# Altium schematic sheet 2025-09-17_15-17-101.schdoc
size 1045 x 355 mm; SheetNumber: 1; SheetTotal: 1
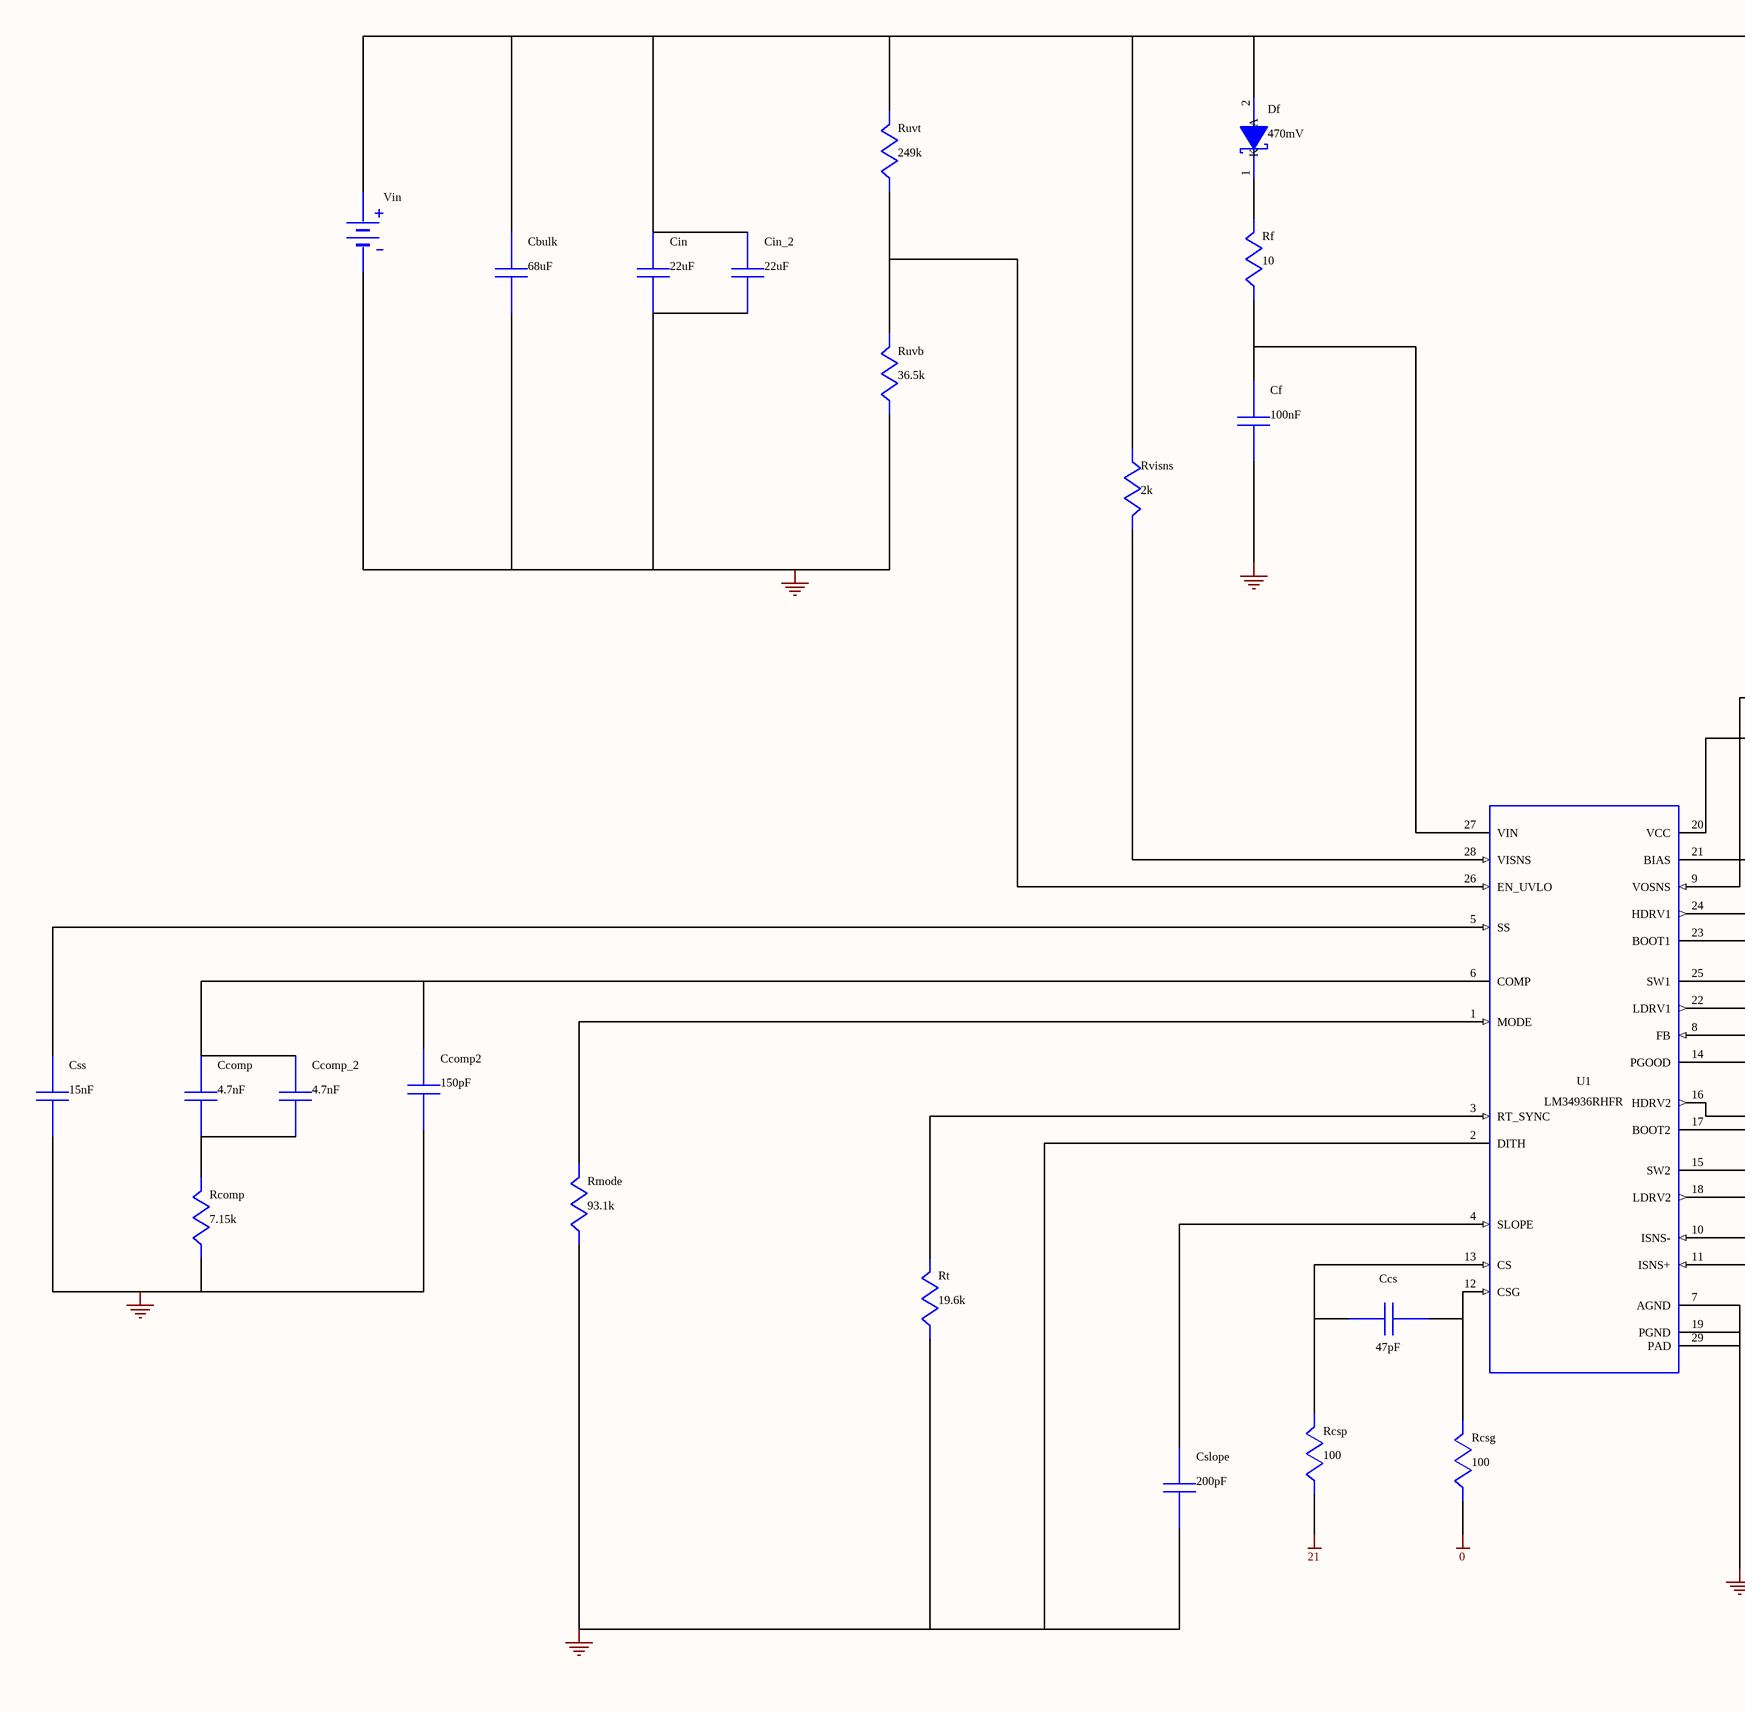
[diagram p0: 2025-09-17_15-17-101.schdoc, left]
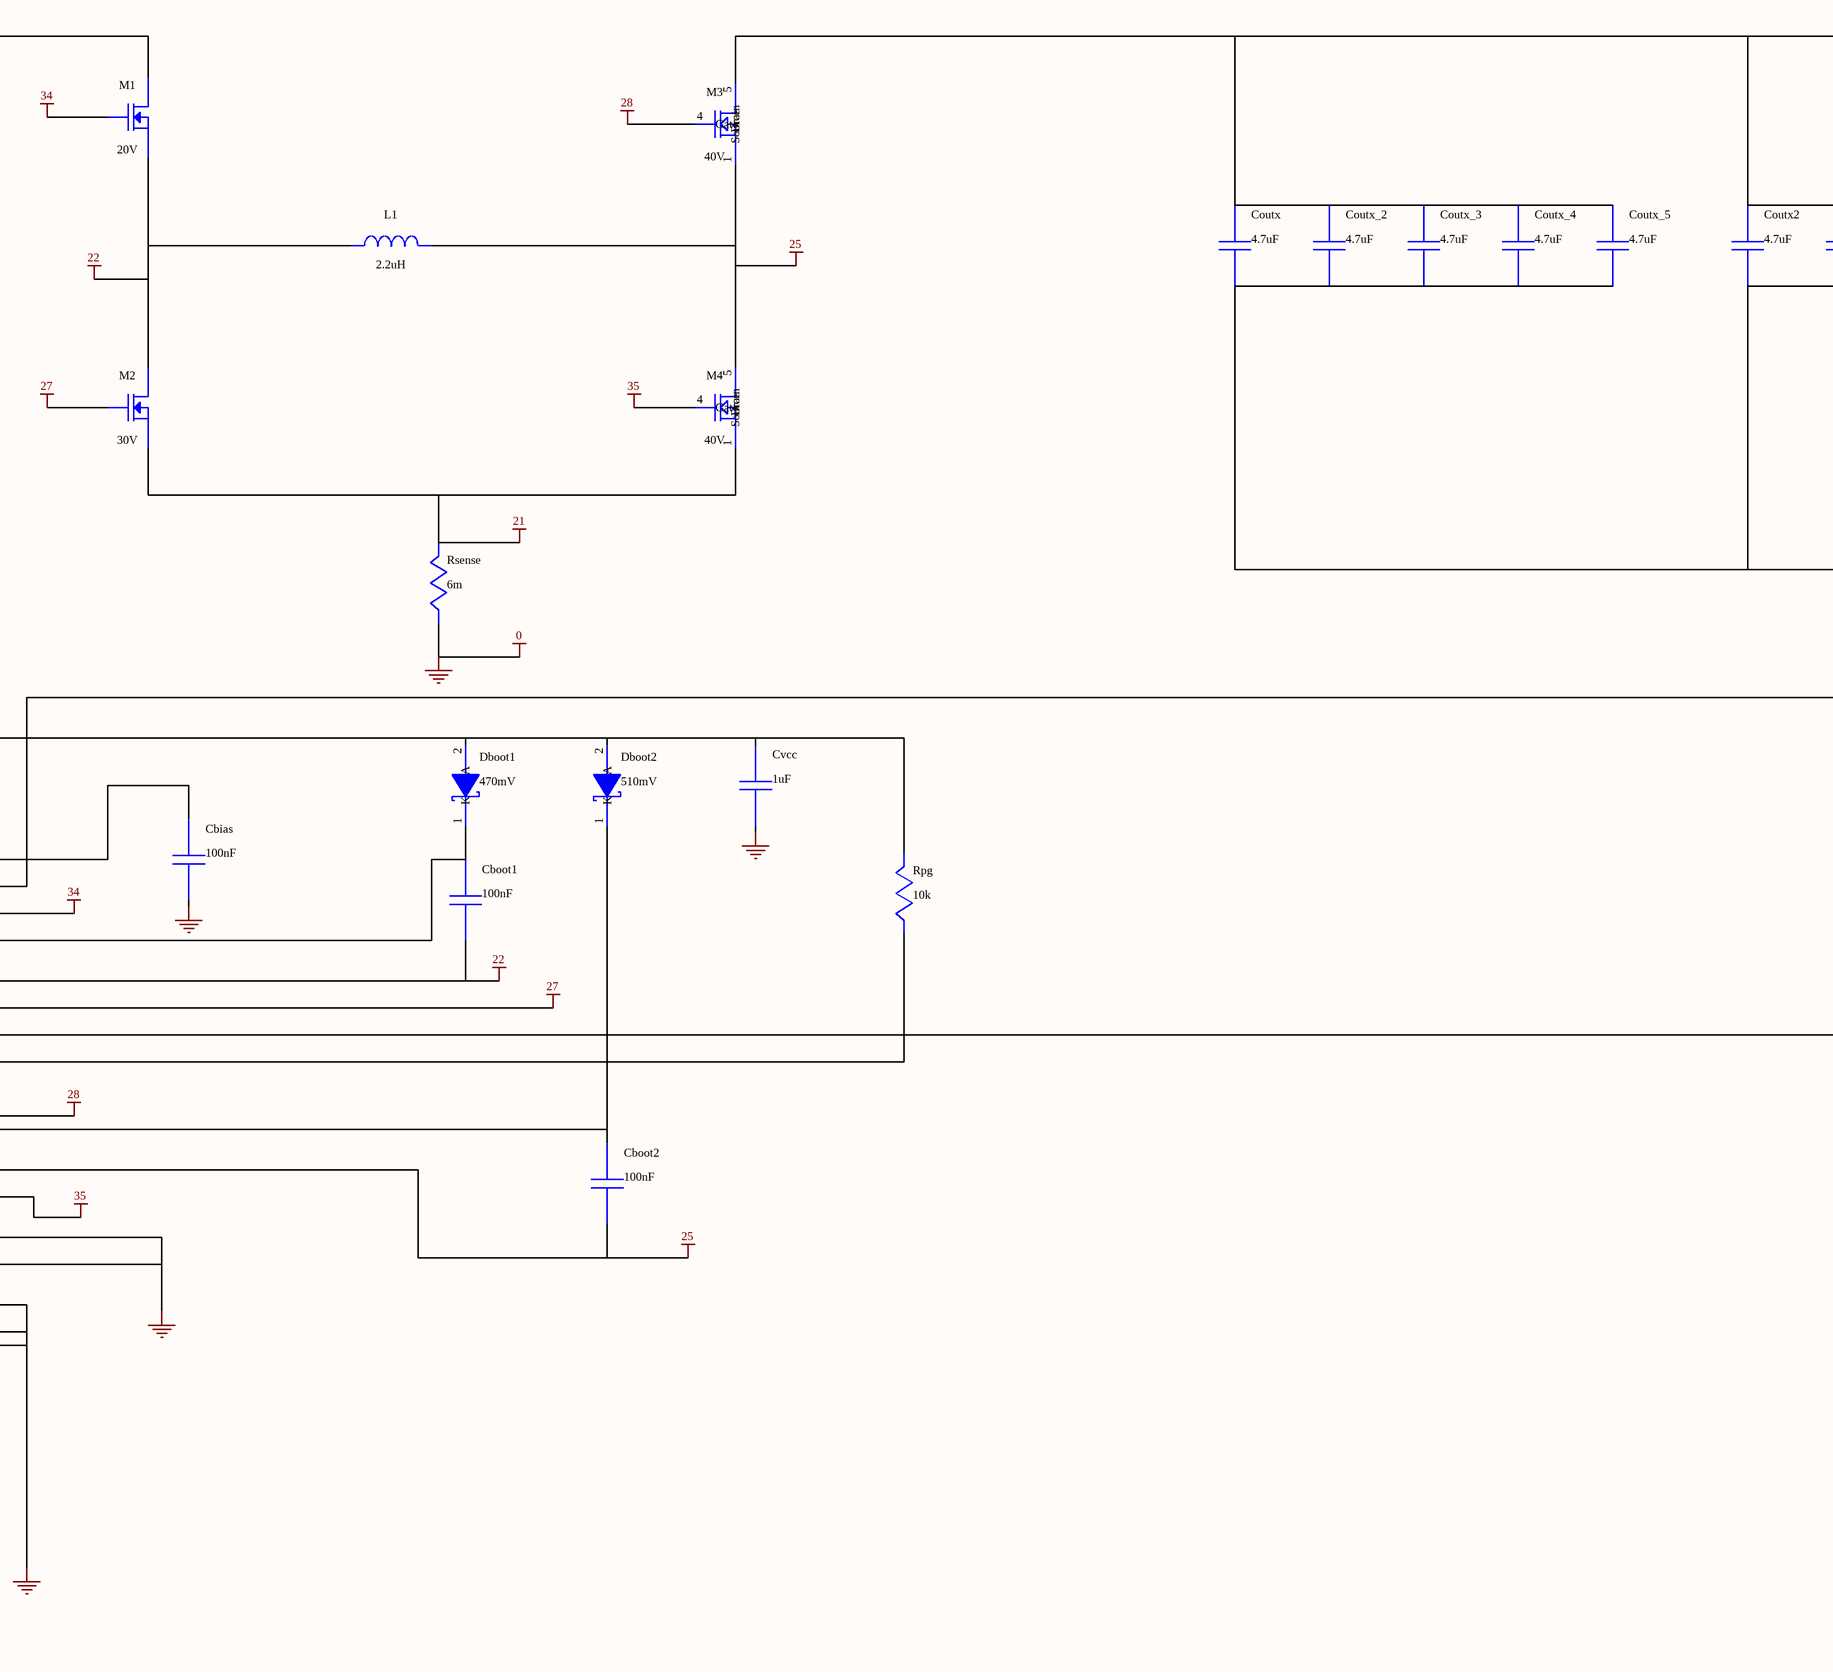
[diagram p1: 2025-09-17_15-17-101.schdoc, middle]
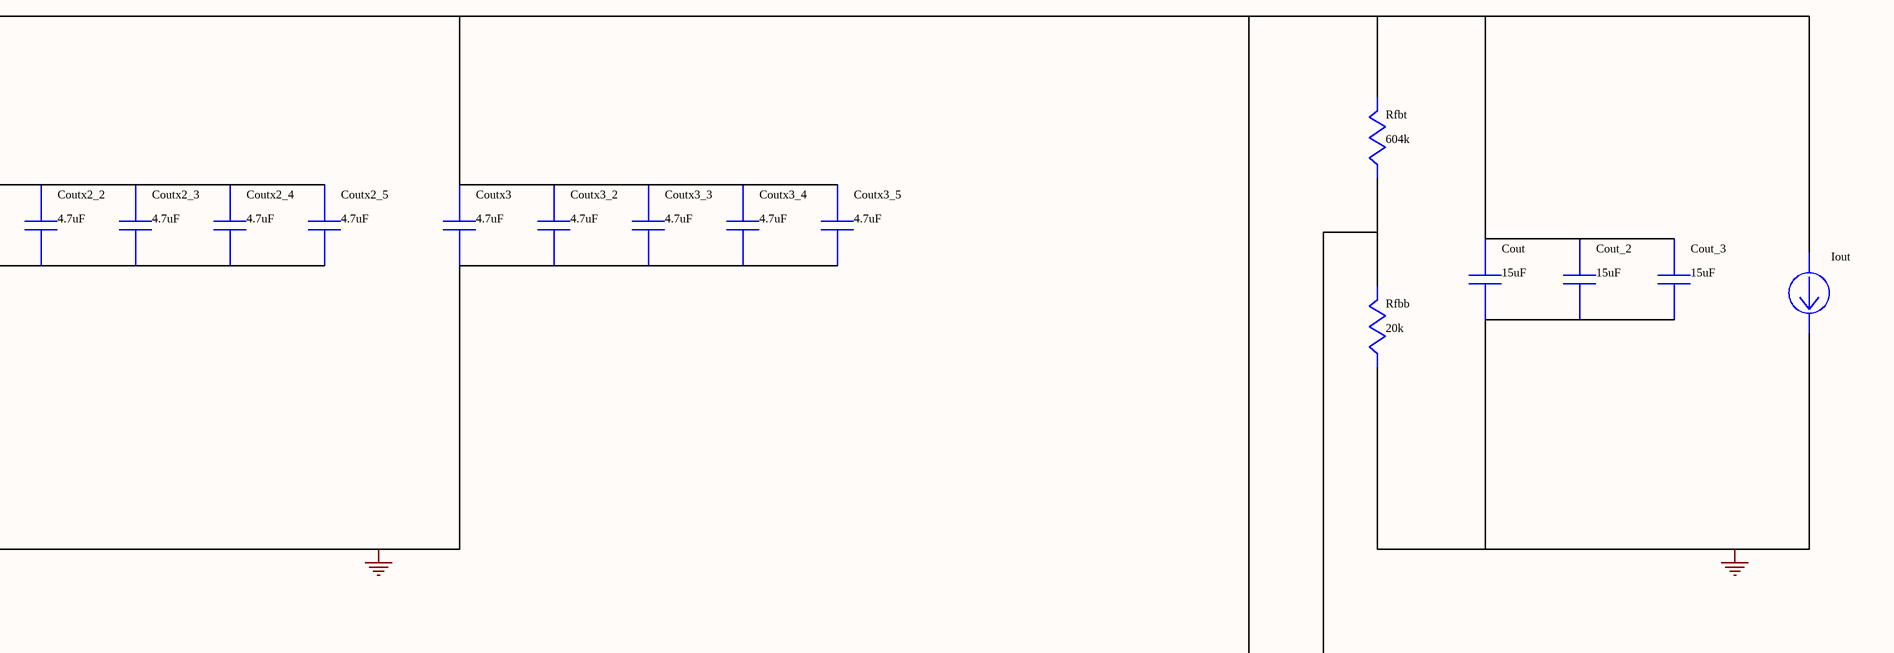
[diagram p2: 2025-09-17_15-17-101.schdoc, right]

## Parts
Cbias  value 100nF  (hidden comment: C0805C104M5RACTU)
Cboot1  value 100nF  (hidden comment: 06033C104KAT2A)
Cboot2  value 100nF  (hidden comment: 06033C104KAT2A)
Cbulk  value 68uF  (hidden comment: GENERIC_CAPACITOR)
Ccomp  value 4.7nF  (hidden comment: CGA2B2X7R1H472K050BA)
Ccomp2  value 150pF  (hidden comment: UMK105CG151JV-F)
Ccomp_2  value 4.7nF  (hidden comment: CGA2B2X7R1H472K050BA)
Ccs  value 47pF  (hidden comment: 06035A470JAT2A)
Cf  value 100nF  (hidden comment: CGA3E2X7R1H104K080AA)
Cin  value 22uF  (hidden comment: MSAST32MSB7226KPNB25)
Cin_2  value 22uF  (hidden comment: MSAST32MSB7226KPNB25)
Cout  value 15uF  (hidden comment: C5750X7S2A156M250KB)
Cout_2  value 15uF  (hidden comment: C5750X7S2A156M250KB)
Cout_3  value 15uF  (hidden comment: C5750X7S2A156M250KB)
Coutx  value 4.7uF  (hidden comment: MSASU21GBB5475KTNA01)
Coutx2  value 4.7uF  (hidden comment: MSASU21GBB5475KTNA01)
Coutx2_2  value 4.7uF  (hidden comment: MSASU21GBB5475KTNA01)
Coutx2_3  value 4.7uF  (hidden comment: MSASU21GBB5475KTNA01)
Coutx2_4  value 4.7uF  (hidden comment: MSASU21GBB5475KTNA01)
Coutx2_5  value 4.7uF  (hidden comment: MSASU21GBB5475KTNA01)
Coutx3  value 4.7uF  (hidden comment: MSASU21GBB5475KTNA01)
Coutx3_2  value 4.7uF  (hidden comment: MSASU21GBB5475KTNA01)
Coutx3_3  value 4.7uF  (hidden comment: MSASU21GBB5475KTNA01)
Coutx3_4  value 4.7uF  (hidden comment: MSASU21GBB5475KTNA01)
Coutx3_5  value 4.7uF  (hidden comment: MSASU21GBB5475KTNA01)
Coutx_2  value 4.7uF  (hidden comment: MSASU21GBB5475KTNA01)
Coutx_3  value 4.7uF  (hidden comment: MSASU21GBB5475KTNA01)
Coutx_4  value 4.7uF  (hidden comment: MSASU21GBB5475KTNA01)
Coutx_5  value 4.7uF  (hidden comment: MSASU21GBB5475KTNA01)
Cslope  value 200pF  (hidden comment: CL10C201JB8NNNC)
Css  value 15nF  (hidden comment: C0603C153J3GACTU)
Cvcc  value 1uF  (hidden comment: EMK107B7105KA-T)
Dboot1  value 470mV  (hidden comment: XBS053V15R-G)
Dboot2  value 510mV  (hidden comment: CDBK0540-HF)
Df  value 470mV  (hidden comment: XBS053V15R-G)
Iout  WB_CURRENT_LOAD  (value not drawn)
L1  value 2.2uH  (hidden comment: SRP1270-2R2M)
M1  value 20V  (hidden comment: CSD15571Q2)
M2  value 30V  (hidden comment: CSD17571Q2)
M3  value 40V  (hidden comment: CSD18514Q5A)
M4  value 40V  (hidden comment: CSD18511Q5A)
Rcomp  value 7.15k  (hidden comment: CRCW04027K15FKED)
Rcsg  value 100  (hidden comment: CRCW0603100RFKEA)
Rcsp  value 100  (hidden comment: CRCW0603100RFKEA)
Rf  value 10  (hidden comment: RC0603FR-0710RL)
Rfbb  value 20k  (hidden comment: RC0603FR-0720KL)
Rfbt  value 604k  (hidden comment: RC0603FR-07604KL)
Rmode  value 93.1k  (hidden comment: RC0603FR-0793K1L)
Rpg  value 10k  (hidden comment: RC0603FR-0710KL)
Rsense  value 6m  (hidden comment: WSR36L000FEA)
Rt  value 19.6k  (hidden comment: CRCW040219K6FKED)
Ruvb  value 36.5k  (hidden comment: AC0402FR-0736K5L)
Ruvt  value 249k  (hidden comment: CRCW0402249KFKED)
Rvisns  value 2k  (hidden comment: CRCW04022K00FKED)
U1  LM34936RHFR
Vin  WB_BATTERY  (value not drawn)

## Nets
0: Cbias.2 Cbulk.2 Ccomp2.2 Cf.2 Cin.2 Cin_2.2 Cout.2 Cout_2.2 Cout_3.2 Coutx.2 Coutx2.2 Coutx2_2.2 Coutx2_3.2 Coutx2_4.2 Coutx2_5.2 Coutx3.2 Coutx3_2.2 Coutx3_3.2 Coutx3_4.2 Coutx3_5.2 Coutx_2.2 Coutx_3.2 Coutx_4.2 Coutx_5.2 Cslope.2 Css.2 Cvcc.2 Iout.2(-) Rcomp.2 Rcsg.2 Rfbb.2 Rmode.2 Rsense.2 Rt.2 Ruvb.2 U1.2(DITH) U1.7(AGND) U1.10(ISNS-) U1.11(ISNS+) U1.19(PGND) U1.29(PAD) Vin.2(-)
21: M2.4(Source) M4.1(Source) M4.2(Source) M4.3(Source) Rcsp.2 Rsense.1
22: Cboot1.2 L1.1 M1.4(Source) M2.1(Drain) M2.2(Drain) M2.5(Drain) M2.6(Drain) U1.25(SW1)
25: Cboot2.2 L1.2 M3.1(Source) M3.2(Source) M3.3(Source) M4.5(Drain) M4.6(Drain) M4.7(Drain) M4.8(Drain) M4.9(Drain) U1.15(SW2)
27: M2.3(Gate) U1.22(LDRV1)
28: M3.4(Gate) U1.16(HDRV2)
34: M1.3(Gate) U1.24(HDRV1)
35: M4.4(Gate) U1.18(LDRV2)
NetCbias_1: Cbias.1 U1.21(BIAS)
NetCboot1_1: Cboot1.1 Dboot1.1(K) U1.23(BOOT1)
NetCboot2_1: Cboot2.1 Dboot2.1(K) U1.17(BOOT2)
NetCbulk_1: Cbulk.1 Cin.1 Cin_2.1 Df.2(A) M1.1(Drain) M1.2(Drain) M1.5(Drain) M1.6(Drain) Ruvt.1 Rvisns.2 Vin.1(+)
NetCcomp_1: Ccomp.1 Ccomp2.1 Ccomp_2.1 U1.6(COMP)
NetCcomp_2: Ccomp.2 Ccomp_2.2 Rcomp.1
NetCcs_1: Ccs.1 Rcsp.1 U1.13(CS)
NetCcs_2: Ccs.2 Rcsg.1 U1.12(CSG)
NetCf_1: Cf.1 Rf.2 U1.27(VIN)
NetCout_1: Cout.1 Cout_2.1 Cout_3.1 Coutx.1 Coutx2.1 Coutx2_2.1 Coutx2_3.1 Coutx2_4.1 Coutx2_5.1 Coutx3.1 Coutx3_2.1 Coutx3_3.1 Coutx3_4.1 Coutx3_5.1 Coutx_2.1 Coutx_3.1 Coutx_4.1 Coutx_5.1 Iout.1(+) M3.5(Drain) M3.6(Drain) M3.7(Drain) M3.8(Drain) M3.9(Drain) Rfbt.1 U1.9(VOSNS)
NetCslope_1: Cslope.1 U1.4(SLOPE)
NetCss_1: Css.1 U1.5(SS)
NetCvcc_1: Cvcc.1 Dboot1.2(A) Dboot2.2(A) Rpg.1 U1.20(VCC)
NetDf_1: Df.1(K) Rf.1
NetRfbb_1: Rfbb.1 Rfbt.2 U1.8(FB)
NetRmode_1: Rmode.1 U1.1(MODE)
NetRpg_2: Rpg.2 U1.14(PGOOD)
NetRt_1: Rt.1 U1.3(RT_SYNC)
NetRuvb_1: Ruvb.1 Ruvt.2 U1.26(EN_UVLO)
NetRvisns_1: Rvisns.1 U1.28(VISNS)

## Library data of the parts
Cbias = C0805C104M5RACTU: Manufacturer Name: Kemet
Cboot1 Cboot2 = 06033C104KAT2A: Manufacturer Name: AVX
Cbulk = GENERIC_CAPACITOR: CUSTOM1; Manufacturer Name: CUSTOM
Ccomp Ccomp_2 = CGA2B2X7R1H472K050BA: CGA2B2X7R1H472K0; Manufacturer Name: TDK
Ccomp2 = UMK105CG151JV-F: Manufacturer Name: Taiyo Yuden
Ccs = 06035A470JAT2A: Manufacturer Name: AVX
Cf = CGA3E2X7R1H104K080AA: CGA3E2X7R1H104K0; Manufacturer Name: TDK
Cin Cin_2 = MSAST32MSB7226KPNB25: MSAST32MSB7226KP; Manufacturer Name: Taiyo Yuden
Cout Cout_2 Cout_3 = C5750X7S2A156M250KB: C5750X7S2A156M25; Manufacturer Name: TDK
Coutx Coutx2 Coutx2_2-Coutx2_5 Coutx3 Coutx3_2-Coutx3_5 Coutx_2-Coutx_5 = MSASU21GBB5475KTNA01: MSASU21GBB5475KT; Manufacturer Name: Taiyo Yuden
Cslope = CL10C201JB8NNNC: Manufacturer Name: Samsung Electro-Mechanics
Css = C0603C153J3GACTU: Manufacturer Name: Kemet
Cvcc = EMK107B7105KA-T: Manufacturer Name: Taiyo Yuden
Dboot1 Df = XBS053V15R-G: Manufacturer Name: Torex USA Corporation
Dboot2 = CDBK0540-HF: Manufacturer Name: Comchip Technology
L1 = SRP1270-2R2M: Manufacturer Name: Bourns
M1 = CSD15571Q2: Manufacturer Name: Texas Instruments
M2 = CSD17571Q2: Manufacturer Name: Texas Instruments
M3 = CSD18514Q5A: Manufacturer Name: Texas Instruments
M4 = CSD18511Q5A: Manufacturer Name: Texas Instruments
Rcomp = CRCW04027K15FKED: Manufacturer Name: Vishay-Dale
Rcsg Rcsp = CRCW0603100RFKEA: Manufacturer Name: Vishay-Dale
Rf = RC0603FR-0710RL: Manufacturer Name: Yageo
Rfbb = RC0603FR-0720KL: Manufacturer Name: Yageo
Rfbt = RC0603FR-07604KL: Manufacturer Name: Yageo
Rmode = RC0603FR-0793K1L: Manufacturer Name: Yageo
Rpg = RC0603FR-0710KL: Manufacturer Name: Yageo
Rsense = WSR36L000FEA: Manufacturer Name: Vishay-Dale
Rt = CRCW040219K6FKED: Manufacturer Name: Vishay-Dale
Ruvb = AC0402FR-0736K5L: Manufacturer Name: Yageo
Ruvt = CRCW0402249KFKED: Manufacturer Name: Vishay-Dale
Rvisns = CRCW04022K00FKED: Manufacturer Name: Vishay-Dale
U1 = LM34936RHFR: Manufacturer Name: Texas Instruments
